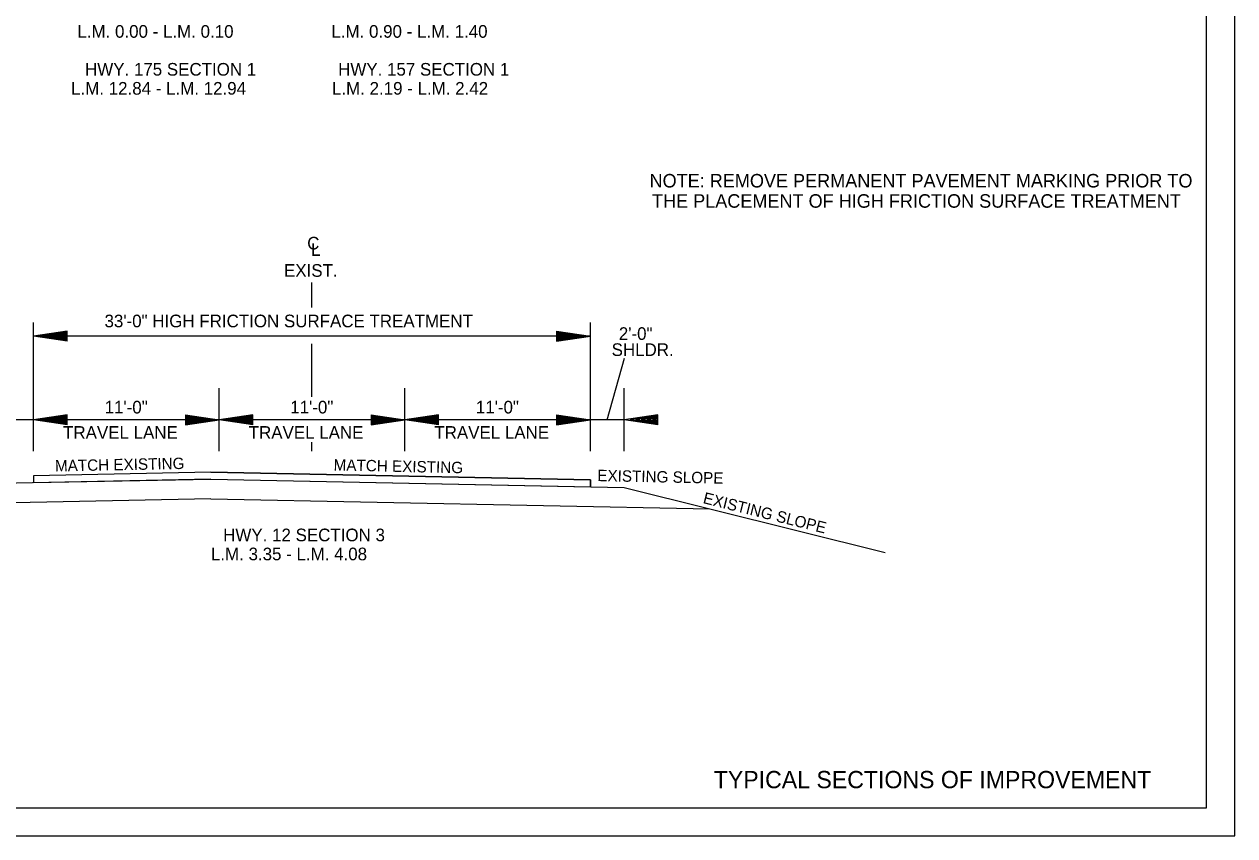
# Model space of a CAD drawing. Extents: x 34757 to 38214, y 51436 to 59430.
# Drawn here: x 35381 to 36457, y 56770 to 57491 of the extents above; entities that cross this region are included whole.
import ezdxf

# ---------------------------------------------------------------- set-up
doc = ezdxf.new("R2010")
doc.units = 0
for name, color, linetype in [('Default', 7, 'Continuous'), ('DSN_DRFT_Junk-No-Plot', 7, 'Continuous'), ('SHET_Border-Lines', 7, 'Continuous')]:
    doc.layers.add(name, color=color, linetype=linetype)

msp = doc.modelspace()

# ---------------------------------------------------------------- linework, layer by layer
at = {"layer": 'Default'}
for p, q in [((35636.3, 57239.3), (35636.3, 57261.3)), ((35388.8, 57111.4), (35388.8, 57225.8)), ((35418.8, 57218.2), (35388.8, 57213.7)), ((35418.8, 57217.4), (35393.8, 57213.7)), ((35418.8, 57209.2), (35418.8, 57218.2)), ((35853.8, 57218.2), (35883.8, 57213.7)), ((35853.8, 57218.2), (35853.8, 57209.2)), ((35853.8, 57217.4), (35878.8, 57213.7)), ((35883.8, 57111.4), (35883.8, 57225.8)), ((35883.8, 57213.7), (35388.8, 57213.7)), ((35418.8, 57209.2), (35388.8, 57213.7)), ((35418.8, 57209.9), (35393.8, 57213.7)), ((35418.8, 57216.7), (35399, 57213.7)), ((35418.8, 57210.7), (35399, 57213.7)), ((35418.8, 57215.9), (35404, 57213.7)), ((35418.8, 57211.4), (35404, 57213.7)), ((35418.8, 57215.1), (35409.1, 57213.7)), ((35418.8, 57212.2), (35409.1, 57213.7)), ((35418.8, 57214.4), (35414.1, 57213.7)), ((35418.8, 57213), (35414.1, 57213.7)), ((35636.3, 57159.8), (35636.3, 57206.9)), ((35853.8, 57216.7), (35873.6, 57213.7)), ((35853.8, 57215.9), (35868.6, 57213.7)), ((35853.8, 57215.1), (35863.6, 57213.7)), ((35853.8, 57214.4), (35858.5, 57213.7)), ((35853.8, 57209.2), (35883.8, 57213.7)), ((35853.8, 57212.2), (35863.6, 57213.7)), ((35853.8, 57210.7), (35873.6, 57213.7)), ((35853.8, 57209.9), (35878.8, 57213.7)), ((35853.8, 57211.4), (35868.6, 57213.7)), ((35853.8, 57213), (35858.5, 57213.7)), ((35898.8, 57139.4), (35914.2, 57194.1)), ((35553.8, 57111.4), (35553.8, 57167.4)), ((35718.8, 57111.4), (35718.8, 57167.4)), ((35913.8, 57111.4), (35913.8, 57167.4)), ((35418.8, 57143.9), (35388.8, 57139.4)), ((35418.8, 57143.2), (35393.8, 57139.4)), ((35418.8, 57142.4), (35399, 57139.4)), ((35418.8, 57141.6), (35404, 57139.4)), ((35418.8, 57134.9), (35418.8, 57143.9)), ((35523.8, 57143.9), (35553.8, 57139.4)), ((35523.8, 57143.9), (35523.8, 57134.9)), ((35523.8, 57143.2), (35548.8, 57139.4)), ((35523.8, 57142.4), (35543.6, 57139.4)), ((35523.8, 57141.6), (35538.6, 57139.4)), ((35583.8, 57143.9), (35553.8, 57139.4)), ((35583.8, 57143.2), (35558.8, 57139.4)), ((35583.8, 57142.4), (35564, 57139.4)), ((35583.8, 57141.6), (35569, 57139.4)), ((35583.8, 57134.9), (35583.8, 57143.9)), ((35688.8, 57143.9), (35718.8, 57139.4)), ((35688.8, 57143.9), (35688.8, 57134.9)), ((35688.8, 57143.2), (35713.8, 57139.4)), ((35688.8, 57142.4), (35708.6, 57139.4)), ((35688.8, 57141.6), (35703.6, 57139.4)), ((35748.8, 57143.9), (35718.8, 57139.4)), ((35748.8, 57143.2), (35723.8, 57139.4)), ((35748.8, 57142.4), (35729, 57139.4)), ((35748.8, 57141.6), (35734, 57139.4)), ((35748.8, 57134.9), (35748.8, 57143.9)), ((35853.8, 57143.9), (35883.8, 57139.4)), ((35853.8, 57143.9), (35853.8, 57134.9)), ((35853.8, 57143.2), (35878.8, 57139.4)), ((35853.8, 57142.4), (35873.6, 57139.4)), ((35853.8, 57141.6), (35868.6, 57139.4)), ((35943.8, 57143.9), (35913.8, 57139.4)), ((35943.8, 57143.2), (35918.8, 57139.4)), ((35943.8, 57142.4), (35924, 57139.4)), ((35943.8, 57141.6), (35929, 57139.4)), ((35943.8, 57134.9), (35943.8, 57143.9)), ((35388.8, 57139.4), (35358.8, 57139.4)), ((35553.8, 57139.4), (35388.8, 57139.4)), ((35418.8, 57134.9), (35388.8, 57139.4)), ((35418.8, 57135.7), (35393.8, 57139.4)), ((35418.8, 57136.4), (35399, 57139.4)), ((35418.8, 57137.2), (35404, 57139.4)), ((35418.8, 57140.9), (35409.1, 57139.4)), ((35418.8, 57138), (35409.1, 57139.4)), ((35418.8, 57140.1), (35414.1, 57139.4)), ((35418.8, 57138.7), (35414.1, 57139.4)), ((35523.8, 57140.9), (35533.6, 57139.4)), ((35523.8, 57140.1), (35528.5, 57139.4)), ((35523.8, 57134.9), (35553.8, 57139.4)), ((35523.8, 57137.9), (35533.6, 57139.4)), ((35523.8, 57136.4), (35543.6, 57139.4)), ((35523.8, 57135.7), (35548.8, 57139.4)), ((35523.8, 57137.2), (35538.6, 57139.4)), ((35523.8, 57138.7), (35528.5, 57139.4)), ((35718.8, 57139.4), (35553.8, 57139.4)), ((35583.8, 57134.9), (35553.8, 57139.4)), ((35583.8, 57135.7), (35558.8, 57139.4)), ((35583.8, 57136.4), (35564, 57139.4)), ((35583.8, 57137.2), (35569, 57139.4)), ((35583.8, 57140.9), (35574.1, 57139.4)), ((35583.8, 57138), (35574.1, 57139.4)), ((35583.8, 57140.1), (35579.1, 57139.4)), ((35583.8, 57138.7), (35579.1, 57139.4)), ((35688.8, 57140.9), (35698.6, 57139.4)), ((35688.8, 57140.1), (35693.5, 57139.4)), ((35688.8, 57134.9), (35718.8, 57139.4)), ((35688.8, 57137.9), (35698.6, 57139.4)), ((35688.8, 57136.4), (35708.6, 57139.4)), ((35688.8, 57135.7), (35713.8, 57139.4)), ((35688.8, 57137.2), (35703.6, 57139.4)), ((35688.8, 57138.7), (35693.5, 57139.4)), ((35883.8, 57139.4), (35718.8, 57139.4)), ((35748.8, 57134.9), (35718.8, 57139.4)), ((35748.8, 57135.7), (35723.8, 57139.4)), ((35748.8, 57136.4), (35729, 57139.4)), ((35748.8, 57137.2), (35734, 57139.4)), ((35748.8, 57140.9), (35739.1, 57139.4)), ((35748.8, 57138), (35739.1, 57139.4)), ((35748.8, 57140.1), (35744.1, 57139.4)), ((35748.8, 57138.7), (35744.1, 57139.4)), ((35853.8, 57140.9), (35863.6, 57139.4)), ((35853.8, 57140.1), (35858.5, 57139.4)), ((35853.8, 57134.9), (35883.8, 57139.4)), ((35853.8, 57137.9), (35863.6, 57139.4)), ((35853.8, 57136.4), (35873.6, 57139.4)), ((35853.8, 57135.7), (35878.8, 57139.4)), ((35853.8, 57137.2), (35868.6, 57139.4)), ((35853.8, 57138.7), (35858.5, 57139.4)), ((35913.8, 57139.4), (35883.8, 57139.4)), ((35943.8, 57134.9), (35913.8, 57139.4)), ((35943.8, 57135.7), (35918.8, 57139.4)), ((35943.8, 57136.4), (35924, 57139.4)), ((35943.8, 57137.2), (35929, 57139.4)), ((35943.8, 57140.9), (35934.1, 57139.4)), ((35943.8, 57138), (35934.1, 57139.4)), ((35943.8, 57140.1), (35939.1, 57139.4)), ((35943.8, 57138.7), (35939.1, 57139.4)), ((35636.3, 57111.4), (35636.3, 57119.4)), ((35546.3, 57092.7), (35388.8, 57089.5)), ((35388.8, 57089.5), (35388.8, 57083.5)), ((35546.3, 57092.7), (35883.8, 57085.9)), ((35546.3, 57086.7), (35358.8, 57082.9)), ((35883.8, 57085.9), (35883.8, 57079.9)), ((35913.8, 57079.3), (36145.8, 57021.3)), ((35546.3, 57069.2), (35282.7, 57063.9)), ((35546.3, 57069.2), (35989.9, 57060.3))]:
    msp.add_line(p, q, dxfattribs=at)
for points in [[(34756.6, 57869.6), (34756.6, 56769.6), (36456.6, 56769.6), (36456.6, 57869.6)], [(35388.8, 57089.5), (35388.8, 57083.5), (35546.3, 57086.7), (35883.8, 57079.9), (35883.8, 57085.9), (35546.3, 57092.7)]]:
    msp.add_lwpolyline(points, close=True, dxfattribs=at)
msp.add_lwpolyline([(35546.3, 57086.7), (35913.8, 57079.3)], dxfattribs=at)
at = {"layer": 'DSN_DRFT_Junk-No-Plot'}
msp.add_lwpolyline([(34756.6, 57869.6), (34756.6, 56769.6), (36456.6, 56769.6), (36456.6, 57869.6)], close=True, dxfattribs=at)
at = {"layer": 'SHET_Border-Lines'}
for points in [[(34756.6, 56769.6), (36456.6, 56769.6), (36456.6, 57869.6), (34756.6, 57869.6)], [(34781.6, 56794.6), (36431.6, 56794.6), (36431.6, 57844.6), (34781.6, 57844.6)]]:
    msp.add_lwpolyline(points, close=True, dxfattribs=at)

# ---------------------------------------------------------------- texts
at = {"layer": 'Default'}
for s, height, p in [('L.M. 0.00 - L.M. 0.10', 11.25, (35427.8, 57479)), ('L.M. 0.90 - L.M. 1.40', 11.25, (35653.6, 57479)), ('HWY. 175 SECTION 1', 11.25, (35434.6, 57445.3)), ('HWY. 157 SECTION 1', 11.25, (35659.6, 57445.3)), ('L.M. 12.84 - L.M. 12.94', 11.25, (35422.2, 57428.4)), ('L.M. 2.19 - L.M. 2.42', 11.25, (35654.1, 57428.4)), ('NOTE: REMOVE PERMANENT PAVEMENT MARKING PRIOR TO ', 12.007, (35936.4, 57345.9)), ('THE PLACEMENT OF HIGH FRICTION SURFACE TREATMENT', 12.007, (35938.6, 57327.9)), ('C', 11.2, (35632.1, 57290.8)), ('L', 11.2, (35635.5, 57285.1)), ('EXIST.', 11.24, (35611.5, 57266.5)), ('33\'-0" HIGH FRICTION SURFACE TREATMENT', 11.25, (35451.9, 57221.6)), ('2\'-0"', 11.25, (35909.1, 57210.4)), ('SHLDR.', 11.25, (35902.7, 57196.1)), ('11\'-0"', 11.25, (35452, 57145)), ('11\'-0"', 11.25, (35617, 57145)), ('11\'-0"', 11.25, (35782, 57145)), ('TRAVEL LANE', 11.25, (35415.1, 57122.5)), ('TRAVEL LANE', 11.25, (35580.1, 57122.5)), ('TRAVEL LANE', 11.25, (35745.1, 57122.5)), ('HWY. 12 SECTION 3', 11.25, (35557.4, 57031.4)), ('L.M. 3.35 - L.M. 4.08', 11.25, (35546.5, 57014.5)), ('TYPICAL SECTIONS OF IMPROVEMENT', 15.349, (35993.5, 56811.9))]:
    msp.add_text(s, height=height, dxfattribs=at).set_placement(p)
for s, rotation, p in [('MATCH EXISTING', 1.146, (35408, 57093.4)), ('MATCH EXISTING', 358.7756, (35655.5, 57094.3)), ('EXISTING SLOPE', 358.7756, (35889.9, 57084.9)), ('EXISTING SLOPE', 345.9632, (35983.3, 57065.4))]:
    msp.add_text(s, height=10.125, rotation=rotation, dxfattribs=at).set_placement(p)

doc.saveas('drawing.dxf')
